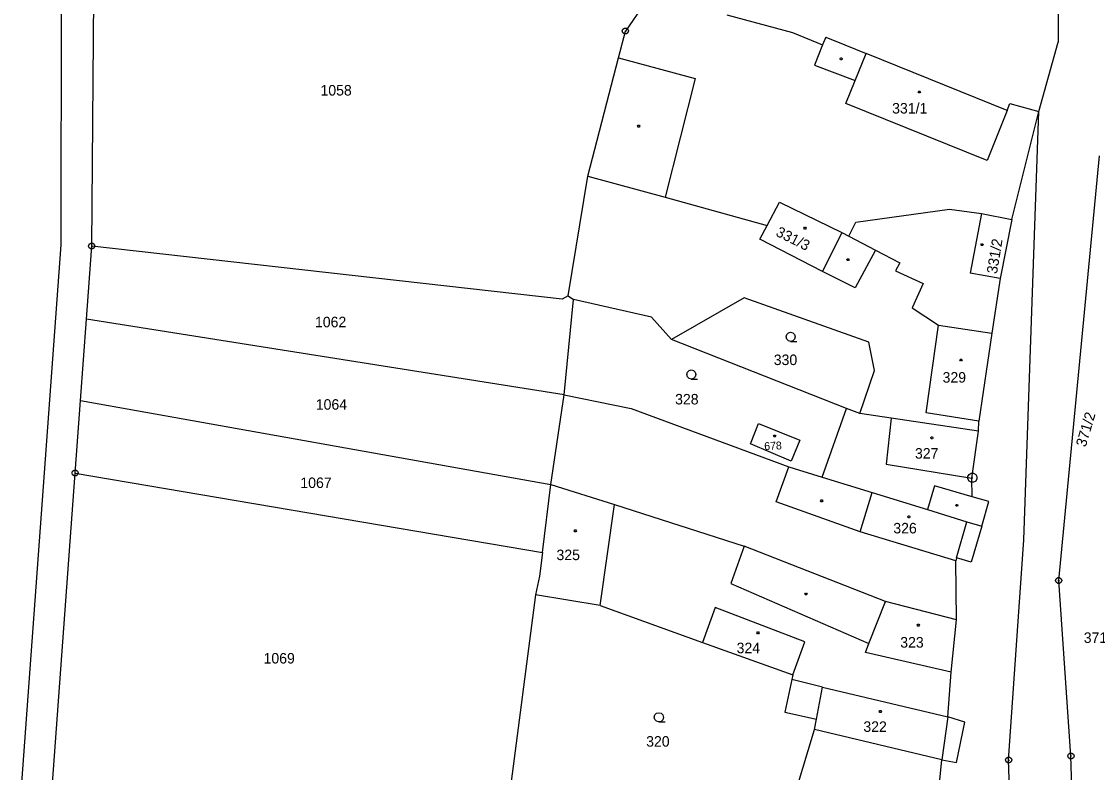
# Model space of a CAD drawing. Extents: x -812394 to -807601, y -1013098 to -1009266.
# Drawn here: x -811179.2 to -811005.4, y -1011411.9 to -1011290.4 of the extents above; entities that cross this region are included whole.
import ezdxf

# ---------------------------------------------------------------- set-up
doc = ezdxf.new("R2010")
doc.units = 0
for name, color, linetype in [('KN_HRANICE', 7, 'Continuous'), ('KN_KULTURY', 7, 'Continuous'), ('KN_MEZNIKY', 7, 'Continuous'), ('KN_PARCELY', 7, 'Continuous'), ('KN_SLUCKY', 7, 'Continuous')]:
    doc.layers.add(name, color=color, linetype=linetype)

# ---------------------------------------------------------------- blocks, each defined once
blk = doc.blocks.new('101')
blk.add_line((-0.05, 0), (0.05, 0))
blk.add_lwpolyline([(0.19, 0.72), (0.53, 0.53), (0.72, 0.19), (0.72, -0.2), (0.53, -0.54), (0.19, -0.73), (-0.2, -0.73), (-0.54, -0.54), (-0.73, -0.2), (-0.73, 0.19), (-0.54, 0.53), (-0.2, 0.72), (0.19, 0.72)])
blk = doc.blocks.new('304')
blk.add_lwpolyline([(0, 0), (-0.38, 0.1), (-0.65, 0.37), (-0.75, 0.74), (-0.65, 1.11), (-0.38, 1.38), (-0.01, 1.48), (0.36, 1.38), (0.63, 1.11), (0.73, 0.73), (0.63, 0.35), (0.36, 0.08), (-0.02, -0.02), (0.98, -0.02)])
blk = doc.blocks.new('NAHRADNI_SYMBOL')
blk.add_lwpolyline([(0.09, 0.15), (0.18, 0), (0.09, -0.15), (-0.09, -0.15), (-0.18, 0), (-0.09, 0.15), (0.09, 0.15)])
blk = doc.blocks.new('402')
blk.add_lwpolyline([(0.09, 0.15), (0.18, 0), (0.09, -0.15), (-0.09, -0.15), (-0.18, 0), (-0.09, 0.15), (0.09, 0.15)])
blk = doc.blocks.new('105')
blk.add_line((-0.12, 0), (0.12, 0))
blk.add_lwpolyline([(0.15, 0.48), (0.4, 0.3), (0.5, 0.01), (0.4, -0.28), (0.15, -0.46), (-0.16, -0.46), (-0.41, -0.28), (-0.51, 0.01), (-0.41, 0.3), (-0.16, 0.48), (0.15, 0.48)])

msp = doc.modelspace()

# ---------------------------------------------------------------- linework, layer by layer
at = {"layer": 'KN_HRANICE'}
for p, q in [((-811172.71, -1011212.32), (-811172.89, -1011326.55)), ((-811167.89, -1011326.74), (-811167.33, -1011261.3)), ((-811011.7, -1011272.27), (-811011.75, -1011293.77)), ((-811078.49, -1011287.34), (-811081.65, -1011291.97)), ((-811065.28, -1011289.37), (-811054.65, -1011292.2)), ((-811082.78, -1011296.33), (-811081.65, -1011291.97)), ((-811054.65, -1011292.2), (-811049.79, -1011294.2)), ((-811049.3, -1011292.98), (-811049.79, -1011294.2)), ((-811049.3, -1011292.98), (-811046.23, -1011294.21)), ((-811046.23, -1011294.21), (-811042.77, -1011295.58)), ((-811014.86, -1011305), (-811011.75, -1011293.77)), ((-811087.72, -1011315.45), (-811082.78, -1011296.33)), ((-811019.97, -1011304.8), (-811042.77, -1011295.58)), ((-811019.97, -1011304.8), (-811019.54, -1011303.71)), ((-811019.54, -1011303.71), (-811014.86, -1011305)), ((-811019.24, -1011322.42), (-811014.86, -1011305)), ((-811017.29, -1011374.24), (-811014.86, -1011305)), ((-811011.64, -1011380.82), (-811005.05, -1011312.16)), ((-811090.93, -1011334.76), (-811087.72, -1011315.45)), ((-811087.72, -1011315.45), (-811075.23, -1011318.84)), ((-811075.23, -1011318.84), (-811058.77, -1011323.4)), ((-811058.77, -1011323.4), (-811056.78, -1011319.65)), ((-811056.78, -1011319.65), (-811046.67, -1011324.57)), ((-811044.44, -1011322.9), (-811029.3, -1011320.76)), ((-811029.3, -1011320.76), (-811024.13, -1011321.49)), ((-811024.13, -1011321.49), (-811019.24, -1011322.42)), ((-811019.24, -1011322.42), (-811021.08, -1011331.96)), ((-811059.96, -1011325.63), (-811058.77, -1011323.4)), ((-811045.56, -1011325.16), (-811044.44, -1011322.9)), ((-811049.8, -1011330.85), (-811059.96, -1011325.63)), ((-811046.67, -1011324.57), (-811049.8, -1011330.85)), ((-811046.67, -1011324.57), (-811045.56, -1011325.16)), ((-811045.56, -1011325.16), (-811041.24, -1011327.41)), ((-811172.89, -1011326.55), (-811179.25, -1011413.51)), ((-811168.76, -1011338.54), (-811167.89, -1011326.74)), ((-811091.86, -1011335.35), (-811167.89, -1011326.74)), ((-811041.24, -1011327.41), (-811037.33, -1011329.45)), ((-811037.33, -1011329.45), (-811038.01, -1011330.76)), ((-811038.01, -1011330.76), (-811033.52, -1011332.81)), ((-811033.52, -1011332.81), (-811035.32, -1011336.75)), ((-811021.08, -1011331.96), (-811022.45, -1011340.81)), ((-811090.93, -1011334.76), (-811091.86, -1011335.35)), ((-811090.93, -1011334.76), (-811090.07, -1011335.38)), ((-811091.55, -1011350.81), (-811090.07, -1011335.38)), ((-811077.44, -1011338.22), (-811090.07, -1011335.38)), ((-811062.47, -1011335.13), (-811074.19, -1011341.86)), ((-811042.3, -1011342.3), (-811062.47, -1011335.13)), ((-811074.19, -1011341.86), (-811077.44, -1011338.22)), ((-811035.32, -1011336.75), (-811031.07, -1011339.53)), ((-811169.72, -1011351.73), (-811168.76, -1011338.54)), ((-811091.55, -1011350.81), (-811168.76, -1011338.54)), ((-811031.07, -1011339.53), (-811022.45, -1011340.81)), ((-811022.45, -1011340.81), (-811024.57, -1011355.07)), ((-811045.94, -1011352.98), (-811074.19, -1011341.86)), ((-811041.39, -1011346.87), (-811042.3, -1011342.3)), ((-811043.78, -1011353.83), (-811041.39, -1011346.87)), ((-811170.58, -1011363.44), (-811169.72, -1011351.73)), ((-811169.72, -1011351.73), (-811093.71, -1011365.29)), ((-811093.71, -1011365.29), (-811091.55, -1011350.81)), ((-811091.55, -1011350.81), (-811080.75, -1011353.03)), ((-811080.75, -1011353.03), (-811055.28, -1011362.43)), ((-811049.84, -1011364.11), (-811045.94, -1011352.98)), ((-811043.78, -1011353.83), (-811045.94, -1011352.98)), ((-811038.69, -1011354.58), (-811043.78, -1011353.83)), ((-811024.6, -1011356.66), (-811038.69, -1011354.58)), ((-811024.6, -1011356.66), (-811024.57, -1011355.07)), ((-811025.7, -1011364.28), (-811024.6, -1011356.66)), ((-811055.28, -1011362.43), (-811049.84, -1011364.11)), ((-811174.26, -1011413.61), (-811170.58, -1011363.44)), ((-811170.58, -1011363.44), (-811095.07, -1011376.26)), ((-811049.84, -1011364.11), (-811041.76, -1011366.61)), ((-811025.62, -1011367.27), (-811025.7, -1011364.28)), ((-811095.07, -1011376.26), (-811093.71, -1011365.29)), ((-811093.71, -1011365.29), (-811083.43, -1011368.52)), ((-811041.76, -1011366.61), (-811032.86, -1011369.35)), ((-811022.94, -1011368.05), (-811025.62, -1011367.27)), ((-811085.72, -1011384.86), (-811083.43, -1011368.52)), ((-811083.43, -1011368.52), (-811062.49, -1011375.27)), ((-811032.86, -1011369.35), (-811026.48, -1011371.32)), ((-811024.09, -1011372.01), (-811022.94, -1011368.05)), ((-811026.48, -1011371.32), (-811024.09, -1011372.01)), ((-811024.09, -1011372.01), (-811025.79, -1011377.87)), ((-811019.73, -1011409.84), (-811017.29, -1011374.24)), ((-811095.07, -1011376.26), (-811095.55, -1011380.13)), ((-811039.64, -1011384.22), (-811062.49, -1011375.27)), ((-811028.16, -1011377.17), (-811028.29, -1011377.65)), ((-811028.16, -1011387.19), (-811028.29, -1011377.65)), ((-811025.79, -1011377.87), (-811028.16, -1011377.17)), ((-811095.55, -1011380.13), (-811096.21, -1011383.14)), ((-811009.67, -1011409.19), (-811011.64, -1011380.82)), ((-811096.21, -1011383.14), (-811100.57, -1011416.83)), ((-811085.72, -1011384.86), (-811096.21, -1011383.14)), ((-811085.72, -1011384.86), (-811069.2, -1011390.82)), ((-811067.16, -1011385.18), (-811069.2, -1011390.82)), ((-811052.68, -1011390.73), (-811067.16, -1011385.18)), ((-811028.16, -1011387.19), (-811039.64, -1011384.22)), ((-811029.04, -1011395.62), (-811028.16, -1011387.19)), ((-811069.2, -1011390.82), (-811054.6, -1011396.09)), ((-811054.6, -1011396.09), (-811052.68, -1011390.73)), ((-811029.55, -1011402.86), (-811029.04, -1011395.62)), ((-811054.76, -1011396.82), (-811055.92, -1011402.11)), ((-811054.6, -1011396.09), (-811054.76, -1011396.82)), ((-811049.83, -1011398.08), (-811054.76, -1011396.82)), ((-811049.83, -1011398.08), (-811029.55, -1011402.86)), ((-811055.92, -1011402.11), (-811050.8, -1011403.23)), ((-811051.11, -1011404.88), (-811050.8, -1011403.23)), ((-811026.8, -1011403.71), (-811029.55, -1011402.86)), ((-811028.15, -1011410.25), (-811026.8, -1011403.71)), ((-811054.01, -1011414.53), (-811051.11, -1011404.88)), ((-811008.13, -1011453.24), (-811009.67, -1011409.19)), ((-811031.22, -1011416.63), (-811030.55, -1011409.8)), ((-811030.55, -1011409.8), (-811028.15, -1011410.25)), ((-811018.24, -1011451.73), (-811019.73, -1011409.84))]:
    msp.add_line(p, q, dxfattribs=at)
msp.add_lwpolyline([(-811060.13, -1011355.42), (-811053.47, -1011358.13), (-811054.85, -1011361.53), (-811061.47, -1011358.7)], close=True, dxfattribs=at)
at = {"layer": 'KN_SLUCKY'}
for p, q in [((-811049.79, -1011294.2), (-811051.11, -1011297.48)), ((-811082.78, -1011296.33), (-811070.38, -1011299.66)), ((-811044.53, -1011299.95), (-811042.77, -1011295.58)), ((-811051.11, -1011297.48), (-811044.53, -1011299.95)), ((-811070.38, -1011299.66), (-811075.23, -1011318.84)), ((-811046.04, -1011303.68), (-811044.53, -1011299.95)), ((-811023.18, -1011312.89), (-811046.04, -1011303.68)), ((-811019.97, -1011304.8), (-811023.18, -1011312.89)), ((-811024.13, -1011321.49), (-811025.93, -1011331.1)), ((-811041.24, -1011327.41), (-811044.55, -1011333.47)), ((-811044.55, -1011333.47), (-811049.8, -1011330.85)), ((-811021.08, -1011331.96), (-811025.93, -1011331.1)), ((-811033.08, -1011353.73), (-811031.07, -1011339.53)), ((-811024.57, -1011355.07), (-811033.08, -1011353.73)), ((-811038.69, -1011354.58), (-811039.52, -1011362.03)), ((-811057.29, -1011368.07), (-811055.28, -1011362.43)), ((-811039.52, -1011362.03), (-811025.7, -1011364.28)), ((-811031.74, -1011365.5), (-811032.86, -1011369.35)), ((-811025.62, -1011367.27), (-811031.74, -1011365.5)), ((-811043.7, -1011372.93), (-811041.76, -1011366.61)), ((-811043.7, -1011372.93), (-811057.29, -1011368.07)), ((-811028.16, -1011377.17), (-811026.48, -1011371.32)), ((-811028.29, -1011377.65), (-811043.7, -1011372.93)), ((-811062.49, -1011375.27), (-811064.61, -1011381.29)), ((-811064.61, -1011381.29), (-811042.3, -1011391.02)), ((-811042.3, -1011391.02), (-811039.64, -1011384.22)), ((-811042.87, -1011392.48), (-811042.3, -1011391.02)), ((-811029.04, -1011395.62), (-811042.87, -1011392.48)), ((-811050.8, -1011403.23), (-811049.83, -1011398.08)), ((-811029.55, -1011402.86), (-811030.55, -1011409.8)), ((-811030.55, -1011409.8), (-811051.11, -1011404.88))]:
    msp.add_line(p, q, dxfattribs=at)

# ---------------------------------------------------------------- block references
at = {"layer": 'KN_KULTURY'}
for name, p in [('402', (-811046.8, -1011296.48)), ('402', (-811034.17, -1011301.82)), ('402', (-811079.52, -1011307.36)), ('402', (-811052.65, -1011323.83)), ('402', (-811024.02, -1011326.52)), ('402', (-811045.71, -1011328.93)), ('304', (-811054.95, -1011342.16)), ('402', (-811027.42, -1011345.16)), ('304', (-811071, -1011348.25)), ('402', (-811057.53, -1011357.46)), ('402', (-811032.14, -1011357.74)), ('402', (-811049.94, -1011367.93)), ('402', (-811028.1, -1011368.67)), ('402', (-811035.86, -1011370.53)), ('NAHRADNI_SYMBOL', (-811089.75, -1011372.79)), ('402', (-811052.48, -1011383)), ('402', (-811034.33, -1011388.04)), ('402', (-811060.25, -1011389.29)), ('304', (-811076.24, -1011403.67)), ('402', (-811040.46, -1011401.99))]:
    msp.add_blockref(name, p, dxfattribs=at)
at = {"layer": 'KN_MEZNIKY'}
for name, p in [('105', (-811081.65, -1011291.97)), ('105', (-811167.89, -1011326.74)), ('105', (-811170.58, -1011363.44)), ('101', (-811025.59, -1011364.2)), ('105', (-811011.64, -1011380.82)), ('105', (-811019.73, -1011409.84)), ('105', (-811009.67, -1011409.19))]:
    msp.add_blockref(name, p, dxfattribs=at)

# ---------------------------------------------------------------- texts
at = {"layer": 'KN_PARCELY'}
for s, p in [('1058', (-811130.94, -1011302.4)), ('331/1', (-811038.56, -1011305.31)), ('1062', (-811131.83, -1011339.87)), ('330', (-811057.69, -1011345.98)), ('329', (-811030.41, -1011348.82)), ('1064', (-811131.7, -1011353.2)), ('328', (-811073.63, -1011352.35)), ('327', (-811034.87, -1011361.11)), ('1067', (-811134.19, -1011365.86)), ('326', (-811038.37, -1011373.2)), ('325', (-811092.8, -1011377.52)), ('323', (-811037.25, -1011391.66)), ('371/1', (-811007.6, -1011390.91)), ('324', (-811063.69, -1011392.57)), ('1069', (-811140.14, -1011394.24)), ('322', (-811043.21, -1011405.29)), ('320', (-811078.31, -1011407.68))]:
    msp.add_text(s, height=1.7, dxfattribs=at).set_placement(p)
for s, height, rotation, p in [('331/3', 1.7, 333.404, (-811057.49, -1011325.01)), ('331/2', 1.7, 80.73, (-811021.62, -1011331.31)), ('371/2', 1.7, 73.51, (-811007.28, -1011359.34)), ('678', 1.27, 2.636, (-811059.2, -1011359.73))]:
    msp.add_text(s, height=height, rotation=rotation, dxfattribs=at).set_placement(p)

doc.saveas('drawing.dxf')
